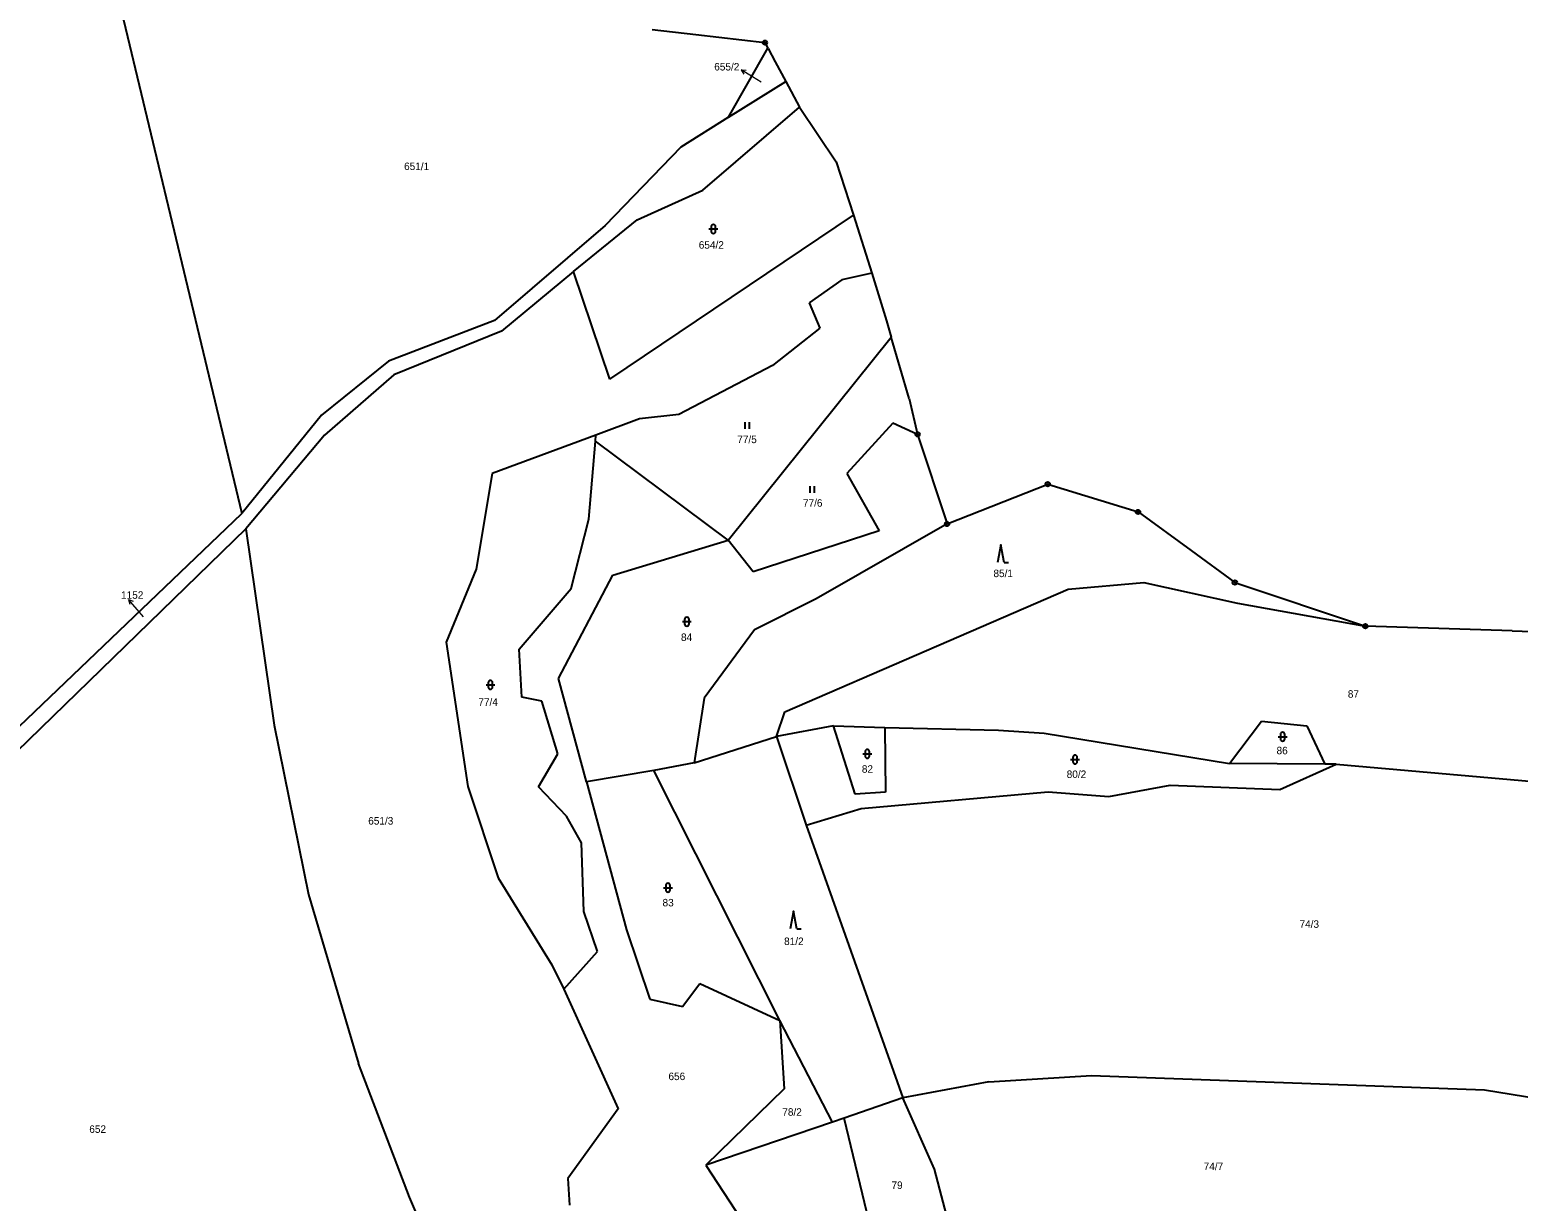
# Model space of a CAD drawing. Extents: x -765428 to -762163, y -1107632 to -1104975.
# Drawn here: x -764128.3 to -763790.9, y -1105750.7 to -1105485.1 of the extents above; entities that cross this region are included whole.
import ezdxf
from ezdxf.enums import TextEntityAlignment as Align

# ---------------------------------------------------------------- set-up
doc = ezdxf.new("R2010")
doc.units = 0
doc.header["$LTSCALE"] = 0.68
for name, color, linetype, lineweight in [('1', 7, 'Continuous', 25), ('3', 7, 'Continuous', 25), ('7', 7, 'Continuous', 13), ('8', 7, 'Continuous', 25)]:
    doc.layers.add(name, color=color, linetype=linetype, lineweight=lineweight)
doc.layers.add('2', color=7, linetype='Continuous')

msp = doc.modelspace()

# ---------------------------------------------------------------- linework, layer by layer
at = {"layer": '1'}
for p, q in [((-764112.29, -1105461.11), (-764080.28, -1105594.81)), ((-763987.26, -1105485.07), (-763977.38, -1105486.22)), ((-763977.38, -1105486.22), (-763961.69, -1105488.04)), ((-763961.69, -1105488.04), (-763961, -1105489.33)), ((-763969.94, -1105504.98), (-763961, -1105489.33)), ((-763960.99, -1105489.35), (-763961, -1105489.33)), ((-763960.99, -1105489.35), (-763959.36, -1105492.4)), ((-763959.36, -1105492.4), (-763956.96, -1105496.89)), ((-763969.94, -1105504.98), (-763956.96, -1105496.89)), ((-763956.96, -1105496.89), (-763953.87, -1105502.67)), ((-763969.94, -1105504.98), (-763980.74, -1105511.74)), ((-763975.8, -1105521.51), (-763953.87, -1105502.67)), ((-763953.87, -1105502.67), (-763945.56, -1105515.11)), ((-763980.74, -1105511.74), (-763997.9, -1105529.49)), ((-763945.56, -1105515.11), (-763941.63, -1105527.2)), ((-763990.68, -1105528.25), (-763975.8, -1105521.51)), ((-764005.1, -1105539.92), (-763990.68, -1105528.25)), ((-763996.81, -1105564.33), (-763941.63, -1105527.2)), ((-763941.63, -1105527.2), (-763937.49, -1105540.31)), ((-763997.9, -1105529.49), (-764023.01, -1105551.03)), ((-764005.1, -1105539.92), (-764021.38, -1105553.5)), ((-763996.81, -1105564.33), (-764005.1, -1105539.92)), ((-763944.26, -1105541.8), (-763951.63, -1105547.01)), ((-763937.49, -1105540.31), (-763944.26, -1105541.8)), ((-763937.49, -1105540.31), (-763934.16, -1105551.09)), ((-763951.63, -1105547.01), (-763949.25, -1105552.79)), ((-764023.01, -1105551.03), (-764047.02, -1105560.23)), ((-763949.25, -1105552.79), (-763959.96, -1105561.27)), ((-763934.16, -1105551.09), (-763933.06, -1105554.83)), ((-764021.38, -1105553.5), (-764045.83, -1105563.37)), ((-763970.06, -1105600.87), (-763933.06, -1105554.83)), ((-763928.97, -1105568.71), (-763933.06, -1105554.83)), ((-764047.02, -1105560.23), (-764062.19, -1105572.54)), ((-763959.96, -1105561.27), (-763981.18, -1105572.35)), ((-764045.83, -1105563.37), (-764061.49, -1105577.05)), ((-763928.97, -1105568.71), (-763927.08, -1105576.86)), ((-764062.19, -1105572.54), (-764080.28, -1105594.81)), ((-763981.18, -1105572.35), (-763990.13, -1105573.36)), ((-763990.13, -1105573.36), (-764000.04, -1105577.03)), ((-763932.7, -1105574.34), (-763943.1, -1105585.76)), ((-763927.08, -1105576.86), (-763932.7, -1105574.34)), ((-764061.49, -1105577.05), (-764079.32, -1105598.31)), ((-764000.04, -1105577.03), (-764023.51, -1105585.72)), ((-764001.6, -1105596.09), (-764000.1, -1105578.41)), ((-763927.08, -1105576.86), (-763920.4, -1105597.18)), ((-764023.51, -1105585.72), (-764027.12, -1105607.45)), ((-763943.1, -1105585.76), (-763935.76, -1105598.76)), ((-763920.4, -1105597.18), (-763897.58, -1105588.15)), ((-763897.58, -1105588.15), (-763877.12, -1105594.44)), ((-764137.93, -1105649.95), (-764080.28, -1105594.81)), ((-764005.64, -1105611.79), (-764001.6, -1105596.09)), ((-763877.12, -1105594.44), (-763865.11, -1105603.19)), ((-764079.32, -1105598.31), (-764131.36, -1105648.87)), ((-764079.32, -1105598.31), (-764072.95, -1105642.76)), ((-763935.76, -1105598.76), (-763964.37, -1105608.03)), ((-763920.4, -1105597.18), (-763950.09, -1105614.17)), ((-763996.17, -1105608.81), (-763970.06, -1105600.87)), ((-763964.37, -1105608.03), (-763970.06, -1105600.87)), ((-763865.11, -1105603.19), (-763855.17, -1105610.44)), ((-764027.12, -1105607.45), (-764033.97, -1105623.97)), ((-764008.49, -1105632.22), (-763996.17, -1105608.81)), ((-764017.38, -1105625.52), (-764005.64, -1105611.79)), ((-763957.16, -1105639.74), (-763892.93, -1105611.95)), ((-763892.93, -1105611.95), (-763875.79, -1105610.41)), ((-763875.79, -1105610.41), (-763854.57, -1105615.13)), ((-763855.17, -1105610.44), (-763825.59, -1105620.35)), ((-763950.09, -1105614.17), (-763964.03, -1105621.17)), ((-763854.57, -1105615.13), (-763825.59, -1105620.35)), ((-763964.03, -1105621.17), (-763975.49, -1105636.67)), ((-763792.32, -1105621.42), (-763825.59, -1105620.35)), ((-763792.32, -1105621.42), (-763774.59, -1105621.99)), ((-764033.97, -1105623.97), (-764029.02, -1105656.67)), ((-764016.82, -1105636.43), (-764017.38, -1105625.52)), ((-764002.16, -1105655.63), (-764008.49, -1105632.22)), ((-764012.23, -1105637.38), (-764016.82, -1105636.43)), ((-763975.49, -1105636.67), (-763977.76, -1105651.32)), ((-764008.64, -1105649.3), (-764012.23, -1105637.38)), ((-763959.09, -1105645.32), (-763957.16, -1105639.74)), ((-764072.95, -1105642.76), (-764065.14, -1105681.14)), ((-763946.13, -1105642.93), (-763959.09, -1105645.32)), ((-763941.26, -1105658.46), (-763946.13, -1105642.93)), ((-763946.13, -1105642.93), (-763934.55, -1105643.34)), ((-763934.55, -1105643.34), (-763934.37, -1105657.97)), ((-763934.55, -1105643.34), (-763908.71, -1105643.93)), ((-763856.38, -1105651.46), (-763849.15, -1105641.88)), ((-763849.15, -1105641.88), (-763838.84, -1105642.94)), ((-763838.84, -1105642.94), (-763834.81, -1105651.62)), ((-763977.76, -1105651.32), (-763959.09, -1105645.32)), ((-763959.09, -1105645.32), (-763952.33, -1105665.47)), ((-763908.71, -1105643.93), (-763898.39, -1105644.63)), ((-763898.39, -1105644.63), (-763856.38, -1105651.46)), ((-764013.04, -1105656.8), (-764008.64, -1105649.3)), ((-763986.86, -1105653.08), (-764002.16, -1105655.63)), ((-763977.76, -1105651.32), (-763986.86, -1105653.08)), ((-763958.28, -1105709.77), (-763986.86, -1105653.08)), ((-763834.81, -1105651.62), (-763856.38, -1105651.46)), ((-763844.99, -1105657.36), (-763832.2, -1105651.65)), ((-763832.2, -1105651.65), (-763834.81, -1105651.62)), ((-763832.2, -1105651.65), (-763721.29, -1105661.33)), ((-764029.02, -1105656.67), (-764022.17, -1105677.39)), ((-764006.65, -1105663.42), (-764013.04, -1105656.8)), ((-764002.16, -1105655.63), (-763993.05, -1105689.15)), ((-763883.77, -1105658.99), (-763869.87, -1105656.42)), ((-763869.87, -1105656.42), (-763844.99, -1105657.36)), ((-763934.37, -1105657.97), (-763941.26, -1105658.46)), ((-763939.88, -1105661.7), (-763897.46, -1105657.88)), ((-763897.46, -1105657.88), (-763883.77, -1105658.99)), ((-764003.25, -1105669.49), (-764006.65, -1105663.42)), ((-763952.33, -1105665.47), (-763939.88, -1105661.7)), ((-763952.33, -1105665.47), (-763930.42, -1105727.26)), ((-764002.74, -1105685.01), (-764003.25, -1105669.49)), ((-764022.17, -1105677.39), (-764010, -1105697.15)), ((-764065.14, -1105681.14), (-764053.84, -1105719.49)), ((-763999.66, -1105694.12), (-764002.74, -1105685.01)), ((-763993.05, -1105689.15), (-763987.76, -1105704.94)), ((-764007.29, -1105702.62), (-763999.66, -1105694.12)), ((-764010, -1105697.15), (-764007.29, -1105702.62)), ((-764007.29, -1105702.62), (-763994.94, -1105729.77)), ((-763980.35, -1105706.54), (-763976.41, -1105701.35)), ((-763976.41, -1105701.35), (-763958.28, -1105709.77)), ((-763987.76, -1105704.94), (-763980.35, -1105706.54)), ((-763946.39, -1105732.81), (-763958.28, -1105709.77)), ((-763958.28, -1105709.77), (-763957.34, -1105725.27)), ((-764042.27, -1105749.83), (-764053.84, -1105719.49)), ((-763910.91, -1105723.65), (-763930.42, -1105727.26)), ((-763910.91, -1105723.65), (-763887.63, -1105722.2)), ((-763887.63, -1105722.2), (-763798.58, -1105725.49)), ((-763957.34, -1105725.27), (-763975.12, -1105742.55)), ((-763930.42, -1105727.26), (-763943.74, -1105731.89)), ((-763923.28, -1105743.48), (-763930.42, -1105727.26)), ((-763798.58, -1105725.49), (-763764.46, -1105730.95)), ((-763994.94, -1105729.77), (-764006.39, -1105745.56)), ((-763946.39, -1105732.81), (-763975.12, -1105742.55)), ((-763943.74, -1105731.89), (-763946.39, -1105732.81)), ((-763938.04, -1105755.42), (-763943.74, -1105731.89)), ((-763975.12, -1105742.55), (-763967.05, -1105754.77)), ((-763917.45, -1105765.63), (-763923.28, -1105743.48)), ((-764006.39, -1105745.56), (-764005.96, -1105751.6)), ((-764031.84, -1105773.8), (-764042.27, -1105749.83))]:
    msp.add_line(p, q, dxfattribs=at)
msp.add_lwpolyline([(-763970.06, -1105600.87), (-764000.1, -1105578.41), (-764000.04, -1105577.03)], dxfattribs=at)
at = {"layer": '3'}
for p, q in [((-763974.381, -1105530.301), (-763972.379, -1105530.301)), ((-763973.881, -1105529.801), (-763973.881, -1105530.802)), ((-763972.879, -1105530.802), (-763972.879, -1105529.801)), ((-763966.201, -1105575.62), (-763966.201, -1105574.12)), ((-763965.2, -1105575.62), (-763965.2, -1105574.12)), ((-763951.471, -1105590.08), (-763951.471, -1105588.58)), ((-763950.47, -1105590.08), (-763950.47, -1105588.58)), ((-763907.45, -1105605.94), (-763906.454, -1105605.94)), ((-763980.391, -1105619.321), (-763978.389, -1105619.321)), ((-763979.891, -1105618.821), (-763979.891, -1105619.822)), ((-763978.889, -1105619.822), (-763978.889, -1105618.821)), ((-764024.911, -1105633.651), (-764022.909, -1105633.651)), ((-764024.411, -1105633.151), (-764024.411, -1105634.152)), ((-764023.409, -1105634.152), (-764023.409, -1105633.151)), ((-763845.351, -1105645.401), (-763843.349, -1105645.401)), ((-763844.851, -1105644.901), (-763844.851, -1105645.902)), ((-763843.849, -1105645.902), (-763843.849, -1105644.901)), ((-763939.491, -1105649.291), (-763937.489, -1105649.291)), ((-763938.991, -1105648.791), (-763938.991, -1105649.792)), ((-763937.989, -1105649.792), (-763937.989, -1105648.791)), ((-763892.391, -1105650.581), (-763890.389, -1105650.581)), ((-763891.891, -1105650.081), (-763891.891, -1105651.082)), ((-763890.889, -1105651.082), (-763890.889, -1105650.081)), ((-763984.671, -1105679.631), (-763982.669, -1105679.631)), ((-763984.171, -1105679.131), (-763984.171, -1105680.132)), ((-763983.169, -1105680.132), (-763983.169, -1105679.131)), ((-763954.48, -1105688.99), (-763953.484, -1105688.99))]:
    msp.add_line(p, q, dxfattribs=at)
for points in [[(-763907.45, -1105605.94), (-763908.2, -1105601.94), (-763908.95, -1105605.94)], [(-763954.48, -1105688.99), (-763955.23, -1105684.99), (-763955.98, -1105688.99)]]:
    msp.add_lwpolyline(points, dxfattribs=at)
for centre, start, end in [((-763973.38, -1105529.8009), 0, 180), ((-763973.38, -1105530.8009), 180, 359.98789), ((-763979.39, -1105618.8209), 0, 180), ((-763979.39, -1105619.8209), 180, 359.98789), ((-764023.91, -1105633.1509), 0, 180), ((-764023.91, -1105634.1509), 180, 359.98789), ((-763844.35, -1105644.9009), 0, 180), ((-763844.35, -1105645.9009), 180, 359.98789), ((-763938.49, -1105648.7909), 0, 180), ((-763938.49, -1105649.7909), 180, 359.98789), ((-763891.39, -1105650.0809), 0, 180), ((-763891.39, -1105651.0809), 180, 359.98789), ((-763983.67, -1105679.1309), 0, 180), ((-763983.67, -1105680.1309), 180, 359.98789)]:
    msp.add_arc(centre, 0.5, start, end, dxfattribs=at)
at = {"layer": '7'}
for p, q in [((-763967.052, -1105494.244), (-763966.452, -1105495.189)), ((-764105.959, -1105614.285), (-764105.68, -1105615.369))]:
    msp.add_line(p, q, dxfattribs=at)
for points in [[(-763962.53, -1105496.98), (-763964.48, -1105495.79), (-763967.052, -1105494.244), (-763965.936, -1105494.331)], [(-764102.54, -1105618.19), (-764103.99, -1105616.55), (-764105.959, -1105614.285), (-764104.924, -1105614.712)]]:
    msp.add_lwpolyline(points, dxfattribs=at)
at = {"layer": '8'}
for centre, radius in [((-763961.69, -1105488.0399), 0.5), ((-763961.69, -1105488.0399), 0.0303), ((-763927.08, -1105576.8599), 0.5), ((-763927.08, -1105576.8599), 0.0303), ((-763897.58, -1105588.1499), 0.5), ((-763897.58, -1105588.1499), 0.0303), ((-763877.12, -1105594.4399), 0.5), ((-763877.12, -1105594.4399), 0.0303), ((-763920.4, -1105597.1799), 0.5), ((-763920.4, -1105597.1799), 0.0303), ((-763855.17, -1105610.4399), 0.5), ((-763855.17, -1105610.4399), 0.0303), ((-763825.59, -1105620.3499), 0.5), ((-763825.59, -1105620.3499), 0.0303)]:
    msp.add_circle(centre, radius, dxfattribs=at)

# ---------------------------------------------------------------- texts
at = {"layer": '2'}
for s, p in [('655/2', (-763967.49, -1105494.365)), ('1152', (-764102.58, -1105614.135))]:
    msp.add_text(s, height=1.7, dxfattribs=at).set_placement(p, align=Align.RIGHT)
for s, p in [('651/1', (-764040.64, -1105516.945)), ('87', (-763828.299, -1105636.565)), ('651/3', (-764048.77, -1105665.325)), ('74/3', (-763838.299, -1105688.725)), ('656', (-763981.659, -1105723.255)), ('78/2', (-763955.539, -1105731.335)), ('652', (-764112.939, -1105735.215)), ('74/7', (-763860.029, -1105743.665)), ('79', (-763931.739, -1105747.925))]:
    msp.add_text(s, height=1.7, dxfattribs=at).set_placement(p, align=Align.CENTER)
for s, p in [('654/2', (-763976.69, -1105534.765)), ('77/5', (-763967.96, -1105578.845)), ('77/6', (-763953.07, -1105593.265)), ('85/1', (-763909.89, -1105609.225)), ('84', (-763980.72, -1105623.705)), ('77/4', (-764026.65, -1105638.405)), ('86', (-763845.72, -1105649.385)), ('82', (-763939.72, -1105653.575)), ('80/2', (-763893.29, -1105654.765)), ('83', (-763984.9, -1105683.875)), ('81/2', (-763957.35, -1105692.635))]:
    msp.add_text(s, height=1.7, dxfattribs=at).set_placement(p)

doc.saveas('drawing.dxf')
